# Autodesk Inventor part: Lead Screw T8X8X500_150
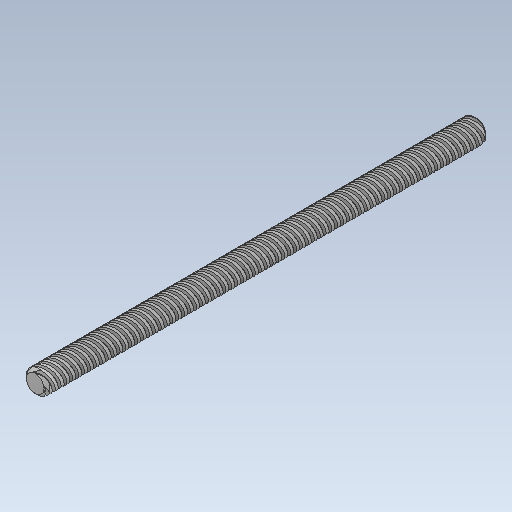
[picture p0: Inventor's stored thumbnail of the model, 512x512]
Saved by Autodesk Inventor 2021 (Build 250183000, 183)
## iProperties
Created: 2026-10
Part Number: Lead Screw T8X8X500_150
Material: Steel
Document SubType Name: Modeling
Designer: hp
Density: 7.85 g/cm^3
Appearance: Default
Author: hp
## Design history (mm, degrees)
feature "Body1"
body "Solid1"
